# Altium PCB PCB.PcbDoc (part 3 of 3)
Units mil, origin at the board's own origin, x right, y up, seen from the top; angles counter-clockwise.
Board outline 3613 x 4415 mil, 2 copper layers (Top Layer, Bottom Layer), stack 62 mil thick; 332 components, 200 nets, 890 pads, 1069 vias.
Unrouted connection lines stored in the file: 1.
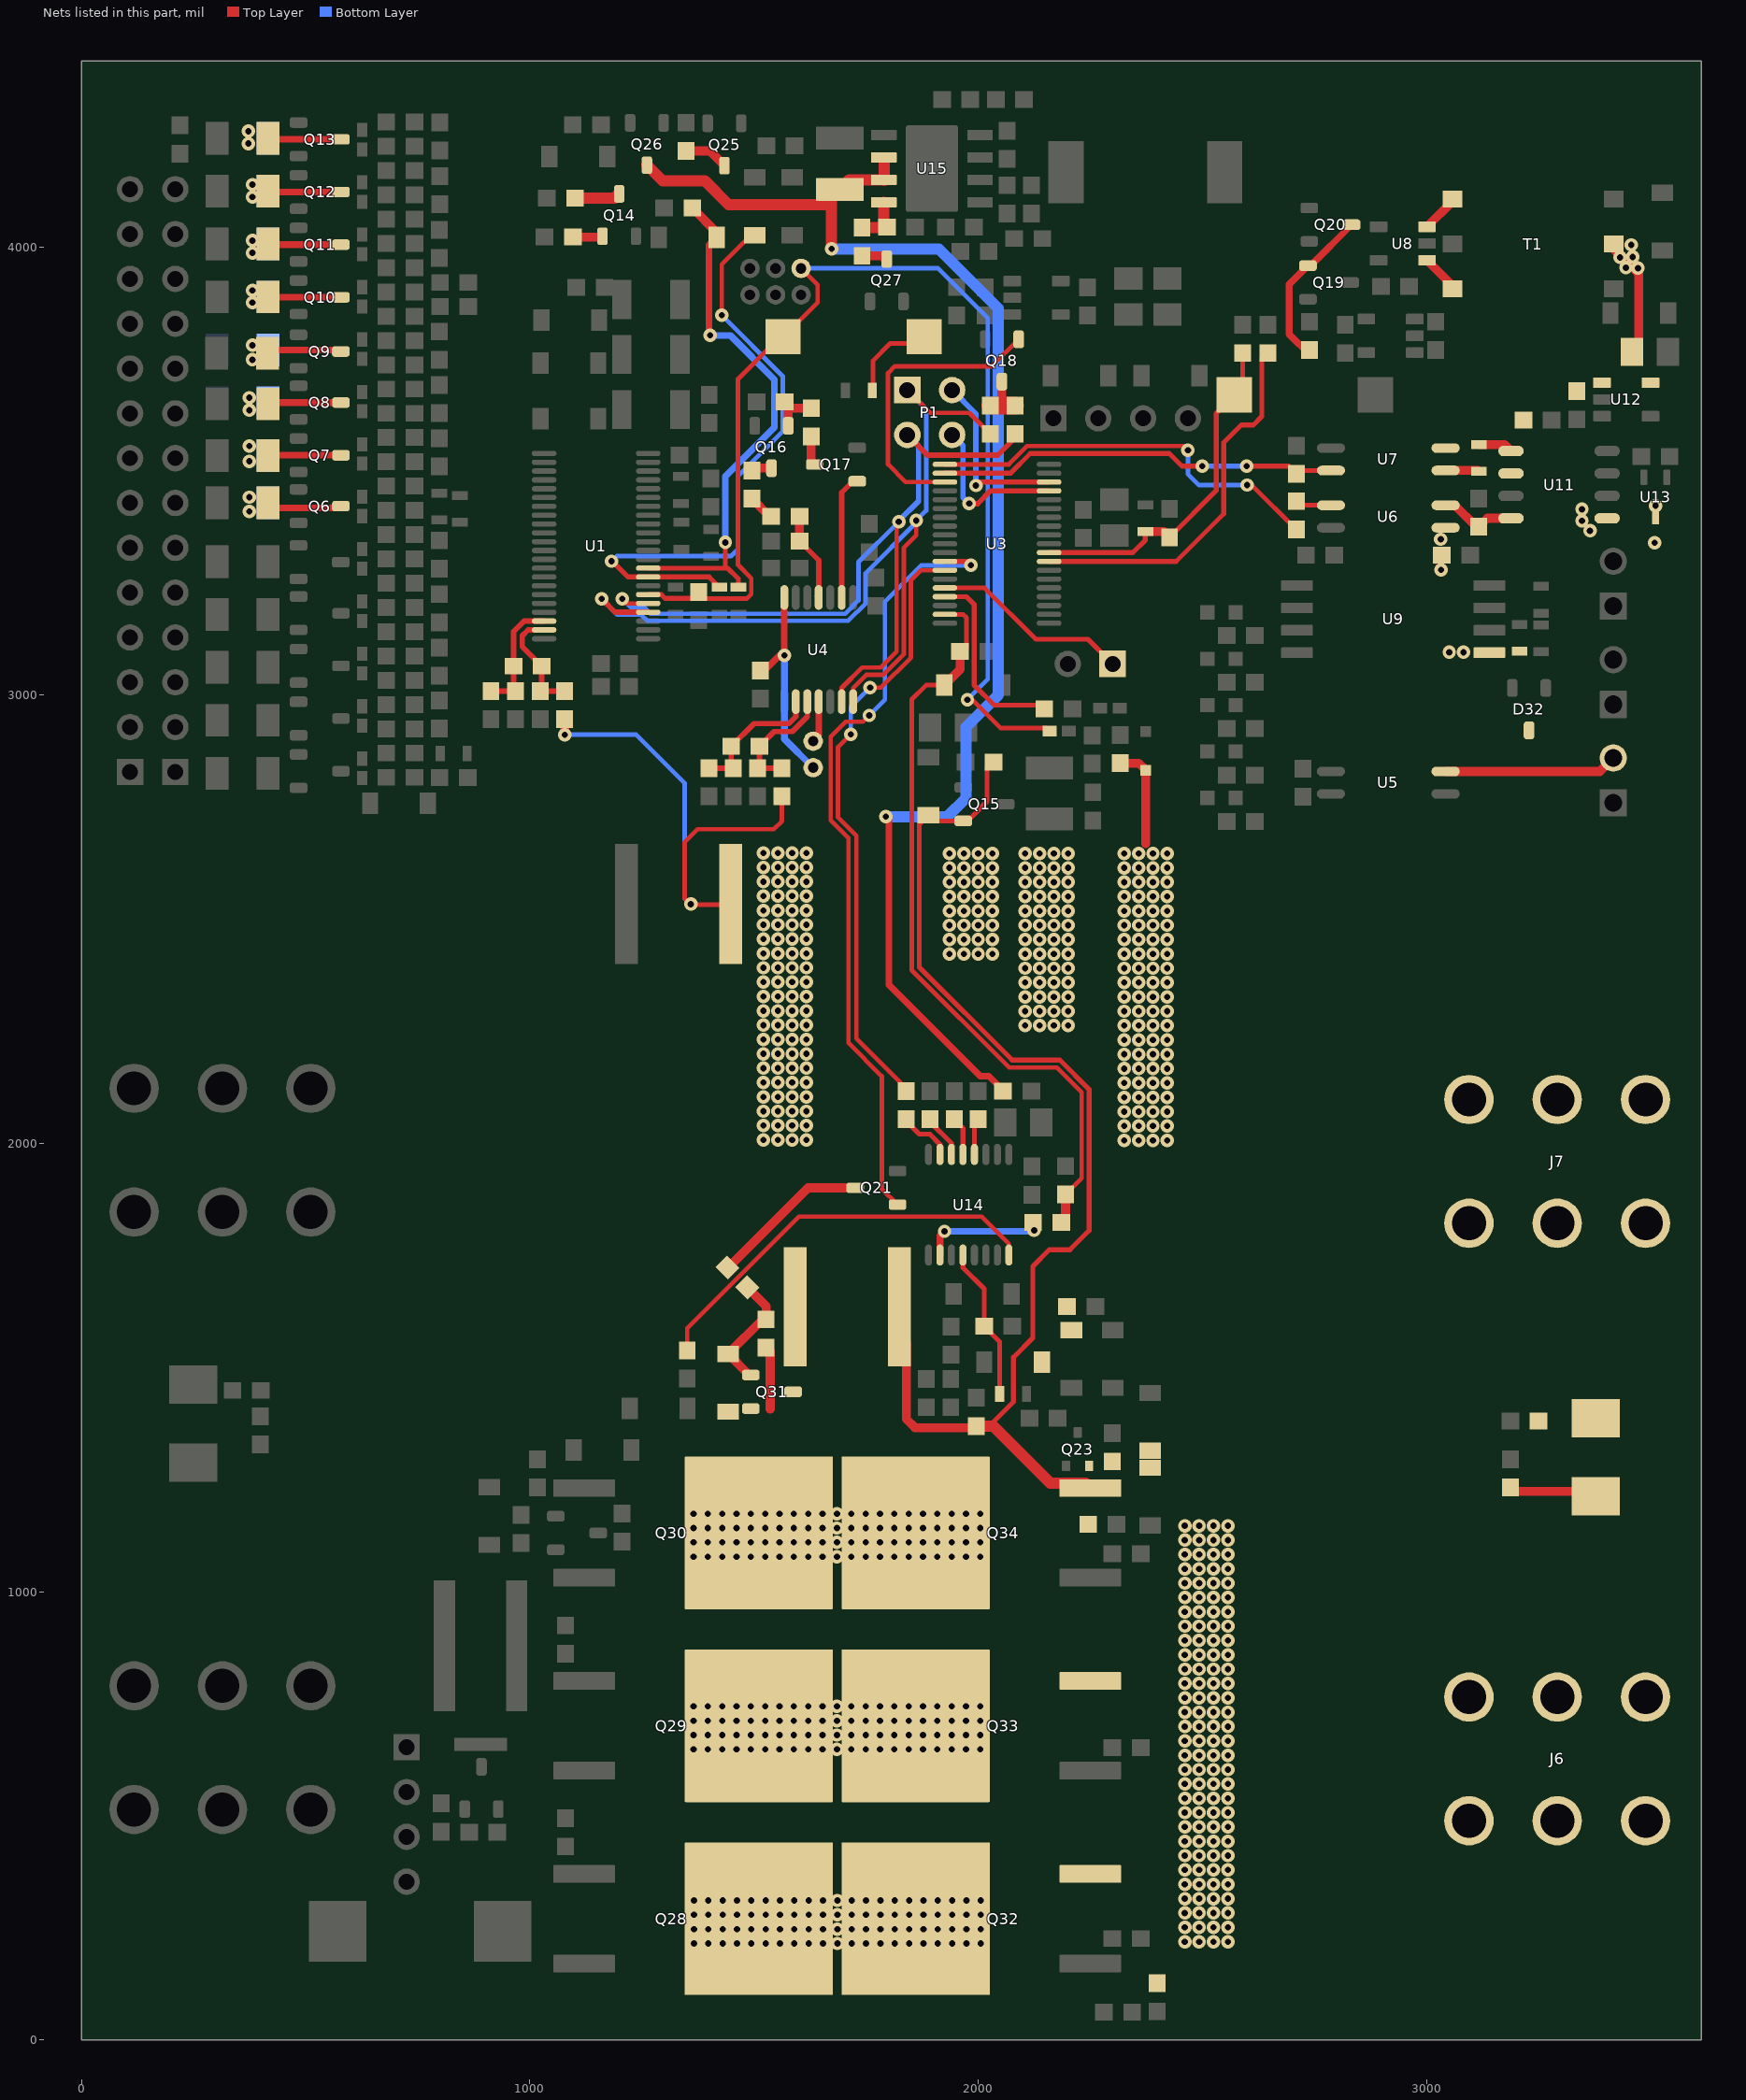
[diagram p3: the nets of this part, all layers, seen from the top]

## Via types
v1: diameter 30, hole 14, Top Layer to Bottom Layer, 1060 vias
v2: diameter 19.68, hole 7.87, Top Layer to Bottom Layer, tented both sides, 4 vias
v3: diameter 19.68, hole 7.87, Top Layer to Bottom Layer, 4 vias
v4: diameter 30, hole 14, Top Layer to Bottom Layer, tented bottom, 1 vias

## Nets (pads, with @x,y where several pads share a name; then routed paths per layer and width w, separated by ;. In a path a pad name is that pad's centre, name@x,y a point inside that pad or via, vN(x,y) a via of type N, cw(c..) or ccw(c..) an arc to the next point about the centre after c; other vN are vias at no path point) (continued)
NetQ6_3: Q6.3 R22.1 R23.1 | length 160.9
  Top Layer w15: R22.1@417.64,3418.06 Q6.3@578.49,3418.06
  other v1: 374,3410 374,3442
NetQ7_3: Q7.3 R24.1 R25.1 | length 161.5
  Top Layer w15: R24.1@417.03,3535.54 Q7.3@578.49,3535.54
  other v1: 374,3522 374,3556
NetQ8_3: Q8.3 R26.1 R27.1 | length 162.1
  Top Layer w15: R26.1@416.43,3653.01 Q8.3@578.49,3653.01
  other v1: 374,3636 374,3664
NetQ9_3: Q9.3 R28.1 R29.1 | length 162.3
  Top Layer w15: R28.1@416.17,3770.49 Q9.3@578.49,3770.49
  other v1: 380.76,3748.6 381,3781
NetQ10_3: Q10.3 R39.1 R40.1 | length 161.7
  Top Layer w15: R39.1@416.78,3887.97 Q10.3@578.49,3887.97
  other v1: 381,3876 381,3903.5
NetQ11_3: Q11.3 R41.1 R42.1 | length 161.1
  Top Layer w15: R41.1@417.38,4005.45 Q11.3@578.49,4005.45
  other v1: 381,3987.04 381,4014.54
NetQ12_3: Q12.3 R43.1 R44.1 | length 160.5
  Top Layer w15: R43.1@417.99,4122.92 Q12.3@578.49,4122.92
  other v1: 381,4112 381,4139.5
NetQ13_3: Q13.3 R45.1 R46.1 | length 159.9
  Top Layer w15: R45.1@418.59,4240.4 Q13.3@578.49,4240.4
  other v1: 372,4231 372,4258.5
NetQ14_1: Q14.1 R47.2 | length 64.3
  Top Layer w20: R47.2@1095.8,4022.42 Q14.1@1160.15,4022.42
NetQ14_3: Q14.3 R48.2 | length 101.2
  Top Layer w25: R48.2@1100.8,4109.42 1188.42,4109.42 Q14.3@1198,4119
NetQ16_1: Q16.1 R69.2 R70.1 | length 110.8
  Top Layer w20: R69.2@1568.5,3655 R69.2@1576.4,3647.09 ; Q16.1@1576.4,3601.24 R69.2@1576.4,3647.09 ; R70.1@1627.4,3640.53 1582.97,3640.53 R69.2@1576.4,3647.09
NetQ16_3: Q16.3 R71.1 | length 46.2
  Top Layer w20: R71.1@1495,3501.5 1500.26,3506.76 Q16.3@1539,3506.76
NetQ17_1: Q17.1 U4.2 | length 269.8
  Top Layer w12: U4.2@1695.58,3218.17 1695.58,3452.58 Q17.1@1720.6,3477.6
NetQ17_3: Q17.3 R70.2 | length 66
  Top Layer w20: R70.2@1627.4,3577.54 1627.4,3523.35 Q17.3@1635.76,3515
NetQ18_1: Q18.1 U3.22 | length 679.5
  Top Layer w10: U3.22@1925.86,3475.8 1838.2,3475.8 1799,3515 1799,3719 1814,3734 2030.16,3734 Q18.1@2090.4,3794.24
  Top Layer w12: Q18.1@2090.4,3784.4 Q18.1@2090.4,3794.24
NetQ18_3: Q18.3 R81.1 R83.1 | length 107.2
  Top Layer w20: 2053,3647.51 Q18.3@2053,3699.76
  Top Layer w40: R81.1@2027.16,3646.08 R83.1@2082.16,3646.08
NetQ19_1: Q19.1 Q20.3 R87.2 | length 369.3
  Top Layer w15: R87.2@2739,3760.5 2694,3805.5 2694,3916.65 Q19.1@2735.76,3958.4 2741.65,3958.4 Q20.3@2833.24,4050
NetQ21_3: Q21.3 R104.1 | length 358
  Top Layer w20: R104.1@1441.79,1722.28 1620.5,1901 Q21.3@1725.76,1901
NetQ25_3: Q25.3 R122.1 | length 99.6
  Top Layer w20: R122.1@1348,4214.5 1401.25,4214.5 Q25.3@1434,4181.76
NetQ27_3: Q27.3 R126.2 | length 59.7
  Top Layer w20: R126.2@1741,3980.5 1784.74,3980.5 Q27.3@1796,3969.24
NetQ31_3: Q31.3 R132.2 R133.2
NetR68_1: R68.1 S1.2 | length 196.4
  Top Layer w10: R68.1@1765.5,3680 1765.5,3746.5 1804,3785 S1.2@1879.48,3785
NetR71_2: R71.2 R72.1 | length 59.9
  Top Layer w20: R71.2@1495,3438.5 1534.5,3399 R72.1@1538.5,3399
NetR72_2: R72.2 R73.2 U4.4 | length 203.5
  Top Layer w12: R73.2@1601.5,3344 1644.4,3301.09 U4.4@1644.4,3218.17 U4.4@1640.91,3221.66
  Top Layer w20: R73.2@1601.5,3344 R72.2@1601.5,3399
NetR86_1: R86.1 U6.1 | length 80.8
  Top Layer w10: R86.1@2709.93,3433 2718.93,3424 U6.1@2787.05,3424
NetR90_1: R90.1 U6.4 U11.4 | length 167.5
  Top Layer w20: U6.4@3042.95,3424 3063,3424 R90.1@3111,3376 ; R90.1@3117,3376 3136,3395 U11.4@3188.72,3395
NetR91_1: R91.1 U7.1 | length 74.9
  Top Layer w20: U7.1@3042.95,3501.5 3115,3501.5 R91.1@3117,3499.5
NetR91_2: R91.2 U11.1 | length 77.7
  Top Layer w20: R91.2@3117,3559.5 3174.22,3559.5 U11.1@3188.72,3545
NetR95_2: R95.2 U14.7 | length 123.6
  Top Layer w11: R95.2@1839.4,2053.95 1839.4,2050.15 1868.66,2020.89 1892.11,2020.89 1914.92,1998.08 U14.7@1914.92,1975.41
NetR96_2: R96.2 U14.6 | length 92.4
  Top Layer w11: R96.2@1892.9,2048.1 1940.51,2000.49 U14.6@1940.51,1975.41
NetR97_2: R97.2 U14.5 | length 86.7
  Top Layer w11: R97.2@1946.4,2053.95 1966.1,2034.25 U14.5@1966.1,1975.41
NetR99_2: R99.2 U14.4 | length 70.3
  Top Layer w11: U14.4@1991.69,1975.41 R99.2@1991.69,2045.75
NetR100_1: R100.1 U14.16 | length 920.7
  Top Layer w10: R100.1@1351,1538.5 1351,1588 1600,1837 2008,1837 2068.46,1776.54 U14.16@2068.46,1751
NetR101_1: R101.1 U14.10 | length 258
  Top Layer w15: U14.10@1914.92,1751 1914.92,1793.92 v1(1925,1804)
  Bottom Layer w15: v1(1925,1804) 2123,1804 v1(2125,1806)
NetR107_2: R107.2 R108.1 U14.12 | length 343.9
  Top Layer w11: U14.12@1966.1,1751 1966.1,1722.9 2013.5,1675.5 R107.2@2013.5,1592 2048,1557.5 R108.1@2048,1441
NetR125_1: R125.1 R126.1 U15.4 | length 100.4
  Top Layer w25: R126.1@1741,4043.5 1781.43,4043.5 1789.72,4051.79 U15.4@1789.72,4100
NetRT4_1: RT4.1 U4.11 | length 93.5
  Top Layer w15: RT4.1@1632,2897.53 1644.4,2909.93 U4.11@1644.4,2985.89
NetT1_1: T1.1 U8.3 | length 85.2
  Top Layer w20: U8.3@3001.45,4045.4 3058.39,4102.35 T1.1@3058.39,4107
NetT1_3: T1.3 U8.1 | length 87.2
  Top Layer w20: U8.1@3001.45,3970.6 3058.39,3913.65 T1.3@3058.39,3907
Pack+: C69.1 C71.1 D16.1 D40.2 D43.2 D48.1 J6.1 J6.2 J6.3 J6.4 J6.5 J6.6 Q15.2 Q23.2 Q32.3 Q33.3 Q34.3 R59.2 R110.2 R114.1 R115.2 R132.1 R133.1 | length 2751.4
  Top Layer w11: Q15.2@1966.77,2719.6 1901.95,2719.6 D16.1@1889.02,2732.53 1868.5,2712.02 1868.5,2393.33 2075.83,2186 2182.33,2186 2247.5,2120.83 2247.5,1805.5 2205,1763 2159,1763 2122,1726 2122,1566 2079,1523 2079,1424.01 2024.5,1369.5 ; Q15.2@1976.6,2719.6 2020,2763 2020,2836.49 R59.2@2034.51,2851 ; Q34.3@2239.55,1231.21 Q34.3@2250.34,1231.21
  Top Layer w20: R132.1@1840,1554.14 1840,1385 1859,1366 R115.2@1980.5,1366 ; C71.1@3182,1224 D48.1@3359.99,1224
  Top Layer w25: R115.2@1996,1369.5 2024.5,1369.5 2033.5,1369.5 2161,1242 Q34.3@2239.55,1242
  other v1: 2461,219 2493,219 2525,219 2557,219 2461,251 2493,251 2525,251 2557,251 2461,283 2493,283 2525,283 2557,283 2461,315 2493,315 2525,315 2557,315 2461,347 2493,347 2525,347 2557,347 2461,379 2493,379 2525,379 2557,379 2461,411 2493,411 2525,411 2557,411 2461,443 2493,443 2525,443 2557,443 2461,475 2493,475 2525,475 2557,475 2461,507 2493,507 2525,507 2557,507 2461,539 2493,539 2525,539 2557,539 2461,571 2493,571 2525,571 2557,571 2461,603 2493,603 2525,603 2557,603 2461,635 2493,635 2525,635 2557,635 2461,667 2493,667 2525,667 2557,667 2461,699 2493,699 2525,699 2557,699 2461,731 2493,731 2525,731 2557,731 2461,763 2493,763 2525,763 2557,763 2461,795 2493,795 2525,795 2557,795 2461,827 2493,827 2525,827 2557,827 2461,859 2493,859 2525,859 2557,859 2461,891 2493,891 2525,891 2557,891 2461,923 2493,923 2525,923 2557,923 2461,955 2493,955 2525,955 2557,955 2461,987 2493,987 2525,987 2557,987 2461,1019 2493,1019 2525,1019 2557,1019 2461,1051 2493,1051 2525,1051 2557,1051 2461,1083 2493,1083 2525,1083 2557,1083 2461,1115 2493,1115 2525,1115 2557,1115 2461,1147 2493,1147 2525,1147 2557,1147
Pack-: C70.2 D21.2 D39.2 D41.2 D48.2 J7.1 J7.2 J7.3 J7.4 J7.5 J7.6 R66.1 R112.1 R118.2 R119.2 R120.1 R127.1 | length 1356.2
  Top Layer w10: R118.2@1429,2533 1359,2533 1345,2547 1345,2672 1374,2701 1544,2701 1562.33,2719.33 R127.1@1562.33,2774.5
  Top Layer w20: v1(1078,2912) R120.1@1078,2945.5 ; R66.1@2317,2848.5 2358.19,2848.5 D21.2@2374,2832.69 2374,2669
  Bottom Layer w10: v1(1078,2912) 1237,2912 1345,2804 1345,2547 v1@1359,2533
  other v1: 2326,2007 2358,2007 2390,2007 2422,2007 1521,2008 1553,2008 1585,2008 1617,2008 2326,2039 2358,2039 2390,2039 2422,2039 1521,2040 1553,2040 1585,2040 1617,2040 2326,2071 2358,2071 2390,2071 2422,2071 1521,2072 1553,2072 1585,2072 1617,2072 2326,2103 2358,2103 2390,2103 2422,2103 1521,2104 1553,2104 1585,2104 1617,2104 2326,2135 2358,2135 2390,2135 2422,2135 1521,2136 1553,2136 1585,2136 1617,2136 2326,2167 2358,2167 2390,2167 2422,2167 1521,2168 1553,2168 1585,2168 1617,2168 2326,2199 2358,2199 2390,2199 2422,2199 1521,2200 1553,2200 1585,2200 1617,2200 2326,2231 2358,2231 2390,2231 2422,2231 1521,2232 1553,2232 1585,2232 1617,2232 2105,2263 2137,2263 2169,2263 2201,2263 2326,2263 2358,2263 2390,2263 2422,2263 1521,2264 1553,2264 1585,2264 1617,2264 2105,2295 2137,2295 2169,2295 2201,2295 2326,2295 2358,2295 2390,2295 2422,2295 1521,2296 1553,2296 1585,2296 1617,2296 2105,2327 2137,2327 2169,2327 2201,2327 2326,2327 2358,2327 2390,2327 2422,2327 1521,2328 1553,2328 1585,2328 1617,2328 2105,2359 2137,2359 2169,2359 2201,2359 2326,2359 2358,2359 2390,2359 2422,2359 1521,2360 1553,2360 1585,2360 1617,2360 2105,2391 2137,2391 2169,2391 2201,2391 2326,2391 2358,2391 2390,2391 2422,2391 1521,2392 1553,2392 1585,2392 1617,2392 1936,2423 1968,2423 2000,2423 2032,2423 2105,2423 2137,2423 2169,2423 2201,2423 2326,2423 2358,2423 2390,2423 2422,2423 1521,2424 1553,2424 1585,2424 1617,2424 1936,2455 1968,2455 2000,2455 2032,2455 2105,2455 2137,2455 2169,2455 2201,2455 2326,2455 2358,2455 2390,2455 2422,2455 1521,2456 1553,2456 1585,2456 1617,2456 1936,2487 1968,2487 2000,2487 2032,2487 2105,2487 2137,2487 2169,2487 2201,2487 2326,2487 2358,2487 2390,2487 2422,2487 1521,2488 1553,2488 1585,2488 1617,2488 1936,2519 1968,2519 2000,2519 2032,2519 2105,2519 2137,2519 2169,2519 2201,2519 2326,2519 2358,2519 2390,2519 2422,2519 1521,2520 1553,2520 1585,2520 1617,2520 1359,2534 1936,2551 1968,2551 2000,2551 2032,2551 2105,2551 2137,2551 2169,2551 2201,2551 2326,2551 2358,2551 2390,2551 2422,2551 1521,2552 1553,2552 1585,2552 1617,2552 1936,2583 1968,2583 2000,2583 2032,2583 2105,2583 2137,2583 2169,2583 2201,2583 2326,2583 2358,2583 2390,2583 2422,2583 1521,2584 1553,2584 1585,2584 1617,2584 1936,2615 1968,2615 2000,2615 2032,2615 2105,2615 2137,2615 2169,2615 2201,2615 2326,2615 2358,2615 2390,2615 2422,2615 1521,2616 1553,2616 1585,2616 1617,2616 1936,2647 1968,2647 2000,2647 2032,2647 2105,2647 2137,2647 2169,2647 2201,2647 2326,2647 2358,2647 2390,2647 2422,2647 1521,2648 1553,2648 1585,2648 1617,2648
Pack_ADC: C50.1 D35.1 R101.2 R102.2 U3.37 | length 1687.5
  Top Layer w10: D35.1@1924.53,3022.59 1883.59,3022.59 1852,2991 1852,2386.5 2069,2169.5 2175.5,2169.5 2231,2114 2231,1922.5 R102.2@2195,1886.5 ; U3.37@1925.86,3180.52 1966.42,3180.52 1974,3172.94 C50.1@1974,3104
  Top Layer w20: D35.1@1924.53,3022.59 1959.5,3057.56 C50.1@1959.5,3098 ; R101.2@2195,1833.5 R102.2@2195,1886.5
PDCHG: Q21.1 U3.31 | length 1755.5
  Top Layer w10: v1(1757,2955) 1743,2941 1704,2941 1671,2908 1671,2721.37 1710.63,2681.74 1710.63,2224.37 1785,2150 1785,1898.84 Q21.1@1820.24,1863.6
  Top Layer w12: U3.31@1925.86,3298.63 v1@1975.63,3298.63
  Bottom Layer w10: v1(1757,2955) 1792,2990 1792,3209 1873,3290 v1(1984,3290)
PDCHG_G: D37.2 Q31.1 R104.2 R106.1 | length 272
  Top Layer w20: R104.2@1485.27,1678.73 1527,1637 R106.1@1527,1607.5 1519.03,1607.5 D37.2@1442,1530.47 Q31.1@1489.07,1483.4
PDCHG_S: D37.1 Q28.2 Q29.2 Q30.2 Q31.2 Q32.2 Q33.2 Q34.2 R106.2 | length 141.2
  Top Layer w20: R106.2@1527,1544.5 1536,1535.5 1536,1407
  other v1: 1366,215 1398,215 1430,215 1462,215 1494,215 1526,215 1558,215 1590,215 1622,215 1654,215 1686,215 1718,215 1750,215 1782,215 1814,215 1846,215 1878,215 1910,215 1942,215 1974,215 2006,215 1366,247 1398,247 1430,247 1462,247 1494,247 1526,247 1558,247 1590,247 1622,247 1654,247 1686,247 1718,247 1750,247 1782,247 1814,247 1846,247 1878,247 1910,247 1942,247 1974,247 2006,247 1366,279 1398,279 1430,279 1462,279 1494,279 1526,279 1558,279 1590,279 1622,279 1654,279 1686,279 1718,279 1750,279 1782,279 1814,279 1846,279 1878,279 1910,279 1942,279 1974,279 2006,279 1366,311 1398,311 1430,311 1462,311 1494,311 1526,311 1558,311 1590,311 1622,311 1654,311 1686,311 1718,311 1750,311 1782,311 1814,311 1846,311 1878,311 1910,311 1942,311 1974,311 2006,311 1365,648 1397,648 1429,648 1461,648 1493,648 1525,648 1557,648 1589,648 1621,648 1653,648 1685,648 1717,648 1749,648 1781,648 1813,648 1845,648 1877,648 1909,648 1941,648 1973,648 2005,648 1365,680 1397,680 1429,680 1461,680 1493,680 1525,680 1557,680 1589,680 1621,680 1653,680 1685,680 1717,680 1749,680 1781,680 1813,680 1845,680 1877,680 1909,680 1941,680 1973,680 2005,680 1365,712 1397,712 1429,712 1461,712 1493,712 1525,712 1557,712 1589,712 1621,712 1653,712 1685,712 1717,712 1749,712 1781,712 1813,712 1845,712 1877,712 1909,712 1941,712 1973,712 2005,712 1365,744 1397,744 1429,744 1461,744 1493,744 1525,744 1557,744 1589,744 1621,744 1653,744 1685,744 1717,744 1749,744 1781,744 1813,744 1845,744 1877,744 1909,744 1941,744 1973,744 2005,744 1365,1078 1397,1078 1429,1078 1461,1078 1493,1078 1525,1078 1557,1078 1589,1078 1621,1078 1653,1078 1685,1078 1717,1078 1749,1078 1781,1078 1813,1078 1845,1078 1877,1078 1909,1078 1941,1078 1973,1078 2005,1078 1365,1110 1397,1110 1429,1110 1461,1110 1493,1110 1525,1110 1557,1110 1589,1110 1621,1110 1653,1110 1685,1110 1717,1110 1749,1110 1781,1110 1813,1110 1845,1110 1877,1110 1909,1110 1941,1110 1973,1110 2005,1110 1365,1142 1397,1142 1429,1142 1461,1142 1493,1142 1525,1142 1557,1142 1589,1142 1621,1142 1653,1142 1685,1142 1717,1142 1749,1142 1781,1142 1813,1142 1845,1142 1877,1142 1909,1142 1941,1142 1973,1142 2005,1142 1365,1174 1397,1174 1429,1174 1461,1174 1493,1174 1525,1174 1557,1174 1589,1174 1621,1174 1653,1174 1685,1174 1717,1174 1749,1174 1781,1174 1813,1174 1845,1174 1877,1174 1909,1174 1941,1174 1973,1174 2005,1174
PMON: R95.1 U3.32 | length 1377.4
  Top Layer w10: v1(1716,2913) 1687,2884 1687,2728 1728.5,2686.5 1728.5,2234.5 1835.97,2127.03 R95.1@1839.4,2127.03 ; v1(1759,3017) 1783,3017 1850,3084 1850,3257 1871.94,3278.94 U3.32@1925.86,3278.94 ; R95.1@1834.57,2122.21 R95.1@1839.4,2117.39
  Bottom Layer w10: v1@1716,2904 v1(1716,2913) 1716,2974 v1(1759,3017)
PRES: P6.1 U3.34 | length 444.4
  Top Layer w10: U3.34@1925.86,3239.57 2014.43,3239.57 2129,3125 2245,3125 P6.1@2300,3070
REG25: C37.1 RT4.2 U4.7 | length 464.7
  Top Layer w15: C37.1@1523.5,3055.5 1557,3089 v1(1568,3089) 1567.63,3089.37 U4.7@1567.63,3218.17
  Bottom Layer w15: v1(1568,3089) 1568,2902.47 RT4.2@1632,2838.47
REGOUT: C30.1 D46.2 U1.8 | length 1396.5
  Top Layer w10: v1(1428,3848) 1428,3961.88 D46.2@1502,4035.88
  Top Layer w11: v1(1182,3299) 1184,3299 1219.03,3263.97 U1.8@1263.98,3263.97 1400.03,3263.97 C30.1@1423,3241
  Bottom Layer w10: v1(1182,3299) 1193.5,3310.5 1448.5,3310.5 1464,3326 1464,3488.33 1564,3588.33 1564,3712 v1(1428,3848)
REGSRC: C13.1 D11.1 R49.2 U1.9 | length 1193.6
  Top Layer w11: U1.9@1263.98,3283.66 1441.34,3283.66 1465,3260 C13.1@1465,3241 ; 1436,3284.66 v1(1436,3341)
  Top Layer w15: v1(1402,3803) 1399.5,3805.5 1399.5,4005.03 D11.1@1416.47,4022
  Top Layer w20: R49.2@1362.5,4087 1416.47,4033.03 D11.1@1416.47,4022
  Bottom Layer w15: v1(1402,3803) 1446.84,3803 1545.5,3704.34 1545.5,3598 1436,3488.5 v1(1436,3341)
RXD: R88.1 U3.21 U7.4 | length 890.8
  Top Layer w11: U3.21@1925.86,3495.48 2072.25,3495.48 2116.27,3539.5 2426.5,3539.5 2455,3511 v1(2500,3511) ; v1(2599,3511) 2693,3511 R88.1@2710,3494 ; R88.1@2717.5,3501.5 U7.4@2787.05,3501.5
  Bottom Layer w11: v1(2500,3511) v1(2599,3511)
SBCLK: R85.1 U3.8 | length 848.8
  Top Layer w11: U3.8@2158.14,3298.63 2441.63,3298.63 2548,3405 2548,3564 2587,3603 2614,3603 2633,3622 2633,3750.5 R85.1@2646,3763.5
SBIO: C38.1 R82.1 R84.1 S2.1 U3.9 | length 795.7
  Top Layer w11: U3.9@2158.14,3318.31 2345.31,3318.31 2373,3346 C38.1@2373,3365 ; R82.1@2427,3352.5 2531,3456.5 2531,3628.48 2571.52,3669 2590,3687.48 R84.1@2590,3763.5 ; S2.1@2569,3656 S2.1@2581.7,3656
  Top Layer w20: C38.1@2373,3365 2414.5,3365 R82.1@2427,3352.5
SCL: P1.3 R83.2 U1.5 U4.13 | length 1812
  Top Layer w10: v1(1206,3215) 1216.08,3204.92 U1.5@1263.98,3204.92 ; U4.13@1695.58,2985.89 1695.58,3016.58 1741,3062 1782.37,3062 1818,3097.63 1818,3382 v1(1823,3387)
  Top Layer w12: P1.3@1842,3581 1887,3536 2044,3536 2082.16,3574.16 R83.2@2082.16,3583.09
  Bottom Layer w10: v1(1206,3215) 1225,3196 1254.63,3196 1268.63,3182 1703.37,3182 1733,3211.63 1733,3297 v1(1823,3387)
  Bottom Layer w12: v1(1823,3387) 1823,3389.18 1867,3433.18 1867,3556 P1.3@1842,3581
SCL-Gauge: P1.4 U3.16 | length 385.8
  Top Layer w12: P1.4@1940,3602 P1.4@1958.91,3583.09 ; v1(1980,3427.59) 1998.79,3427.59 2027.32,3456.11 U3.16@2158.14,3456.11
  Bottom Layer w12: P1.4@1942,3581 1966,3557 1966,3441.59 v1(1980,3427.59)
SDA: P1.1 R81.2 U1.4 U4.14 | length 2001.5
  Top Layer w10: U4.14@1721.17,2985.89 1721.17,3016.17 1751,3046 1789,3046 1834,3091 1834,3329 1862,3357 v1(1862,3390) ; P1.1@1842,3681 1893,3630 1980.25,3630 R81.2@2027.16,3583.09
  Top Layer w12: v1(1160,3215) 1189.77,3185.23 U1.4@1263.98,3185.23
  Bottom Layer w10: v1(1160,3215) 1195,3180 1248,3180 1262,3166 1710,3166 1749,3205 1749,3272.63 1862,3385.63 v1(1862,3390) 1884,3412 1884,3639 P1.1@1842,3681
SDA-Gauge: P1.2 U3.17 | length 442.6
  Top Layer w10: P1.2@1940,3677 P1.2@1940,3702
  Top Layer w12: v1(1995,3468) 2002.8,3475.8 U3.17@2158.14,3475.8
  Bottom Layer w12: P1.2@1940,3702 P1.2@1951.5,3690.5 ; P1.2@1942,3681 1995,3628 v1(1995,3468)
SGND: C41.2 C43.2 C45.1 C46.2 C47.2 D32.3 J5.2 T1.5 U5.2 U6.3 U7.2 U9.5 U11.2 U11.5 U12.1 U12.5 U13.3 | length 653.3
  Top Layer w15: C43.2@3022,3300.5 C43.2@3034.5,3313
  Top Layer w20: U5.2@3042.95,2830 3387,2830 J5.2@3417,2860 ; T1.5@3418.24,4007 3418.24,3995.76 3474,3940 C46.2@3474,3781
  other v1: 3051,3096 3083,3096 3033,3280 3509,3340 3032,3348 3365,3367 3347,3389 3347,3415 3511,3423 3472,3953 3445,3954 3432,3977 3460,3978 3457,4005
SRN: C60.1 C61.2 R127.2 U4.10 | length 272.3
  Top Layer w12: R127.2@1562.33,2837.5 C61.2@1508,2837.5 1511.99,2841.49 C60.1@1511.99,2886 1544.99,2919 1585.46,2919 1618.81,2952.36 U4.10@1618.81,2985.89
SRN_M: C56.1 C57.2 R120.2 U1.43 | length 251.9
  Top Layer w12: U1.43@1031.69,3145.86 995.86,3145.86 983,3133 983,3108.5 C56.1@1026.5,3065 1026.5,3013.64 1022.36,3009.5 C57.2@1023,3009.5 R120.2@1077,3009.5
SRP: C58.1 C60.2 R124.2 U4.9 | length 310
  Top Layer w12: R124.2@1399.33,2837.5 C58.1@1453.6,2837.5 1449,2842.1 C60.2@1449,2886 1500,2937 1578,2937 1593.22,2952.22 U4.9@1593.22,2985.89
SRP_M: C55.1 C56.2 R117.2 U1.42 | length 267.3
  Top Layer w12: R117.2@913.07,3009.5 C55.1@968,3009.5 963.5,3013.99 C56.2@963.5,3065 963.5,3142.05 987,3165.55 U1.42@1031.69,3165.55
TS1: C29.1 D22.1 RT1.2 S1.1 U1.6 | length 2633.3
  Top Layer w10: C29.1@1377,3230.5 1391.5,3216 1484,3216 1494,3226 1494,3261 1464.14,3290.86 1464.14,3705.44 S1.1@1543.7,3785 ; S1.1@1564.52,3785 1551,3785 1642,3876 1642,3915.53 RT1.2@1605,3952.53 ; v1(1976,2990) 1987,2990 2050,2927 2152.35,2927 D22.1@2159.35,2920
  Top Layer w11: U1.6@1263.98,3224.6 1293.4,3224.6 1302,3216 1362.5,3216 C29.1@1377,3230.5
  Bottom Layer w10: RT1.2@1605,3952.53 1910.47,3952.53 2021.5,3841.5 2021.5,3035.5 v1(1976,2990)
TXD: R86.2 U3.20 | length 909.1
  Top Layer w10: U3.20@1925.86,3515.17 2068.6,3515.17 2109.43,3556 2459,3556 v1(2468,3547) ; v1(2600,3469) 2610.94,3469 R86.2@2709.93,3370
  Bottom Layer w10: v1(2468,3547) 2468,3494 2493,3469 v1(2600,3469)
VDD: C59.1 Q26.3 R98.2 U15.2 U15.3 | length 3173.7
  Top Layer w15: v1@1800.63,2722.87 1800.63,2354 2004.5,2150.13 2024.19,2150.13 2055.5,2118.82 R98.2@2055.5,2117
  Top Layer w25: Q26.3@1261,4182.76 1295.76,4148 1390,4148 1443.09,4094.91 1657,4094.91 ; v1(1673,3996) C59.1@1673,4110.91 ; C59.1@1691,4128.91 1712.09,4150 U15.3@1789.72,4150 ; U15.3@1790,4149 U15.2@1790,4199
  Bottom Layer w25: v1(1673,3996) 1912,3996 2045,3863 2045,3000.94 1972.53,2928.47 1972.53,2770.2 1931.32,2729 1794,2729 v1(1794,2729.5)
Wake: R61.2 U3.35 | length 427.3
  Top Layer w11: U3.35@1925.86,3219.89 1974.11,3219.89 1991,3203 1991,3023 2036,2978 R61.2@2147.5,2978
pads on no net: U1.21 U1.22 U1.23 U3.13 U3.14 U3.15 U3.19 U3.26 U3.28 U3.29 U3.30 U3.36 U3.38 U14.3 U14.13 U14.14 U14.15 U15.6 U15.9@1897,4175

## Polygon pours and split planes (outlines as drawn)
3V3 on Top Layer "TOP_LAYER_3V3_P184" (solid, remove dead copper, pour order 184): 2034.47,3869 2034.47,3771 1933.3,3771 1933.3,3869
CHG_S on Top Layer "TOP_LAYER_CHG_S_P078" (solid, remove dead copper, pour order 78): 949,1143 873,1143 873,1099 928,1041 1277,1041 1277,1143
GND on Top Layer "TOP_LAYER_GND_P194" (solid, remove dead copper, pour order 194): 1801,1999 1801,1854 2139,1854 2139,1999
Pack- on Top Layer "TOP_LAYER_PACK-_P192" (solid, remove dead copper, pour order 192): 1420,2675 1800,2675 1800,1875 1574,1875 1544,1845 1544,1511 1420,1511
NetC20_1 on Top Layer "TOP_LAYER_NETC20_1_P188" (solid, remove dead copper, pour order 188): 2105.87,2868 2105.87,2814 2187.3,2814 2237.3,2764 2275,2764 2275,2868
CHG_S on Top Layer "TOP_LAYER_CHG_S_P174" (solid, pour order 174): 991,611 938,558 938,424 982,424 1015,457 1015,587
NetC54_1 on Top Layer "TOP_LAYER_NETC54_1_P172" (solid, remove dead copper, pour order 172): 825,508 825,611 754,682 695,682 695,508
GND on Top Layer "TOP_LAYER_GND_P170" (solid, remove dead copper, pour order 170): 825,485 825,414 771,360 771,318 678,318 678,485
Pack+ on Top Layer "TOP_LAYER_PACK+_P080" (solid, remove dead copper, pour order 80): 2408,1311 2258,1311 2216,1269 2216,1249 2408,1249
Pack+ on Top Layer "TOP_LAYER_PACK+_P064" (solid, remove dead copper, pour order 64): 3561,1255 2182,1255 2182,106 3561,106
Pack- on Top Layer "TOP_LAYER_PACK-_P062" (solid, remove dead copper, pour order 62): 3561,2673 1871,2673 1871,1345 3561,1345
GND on Top Layer "TOP_LAYER_GND_P058" (solid, remove dead copper, pour order 58): 2686,3631 2686,3748 2686,4057 3047,4057 3047,3752 2926,3631
GND on Top Layer "TOP_LAYER_GND_P054" (solid, remove dead copper, pour order 54): 2796.21,3613.21 2748,3565 2748,3535 2819,3535 2819,3590.43
GND on Top Layer "TOP_LAYER_GND_P052" (solid, remove dead copper, pour order 52): 2780,3388 2758.71,3388 2740,3369.29 2740,3338 2597,3338 2597,3316 2641,3272 2763,3272 2763,3344 2819,3344 2819,3388
GND on Top Layer "TOP_LAYER_GND_P050" (solid, remove dead copper, pour order 50): 2755,2817 2755,2833.93 2793,2871.93 2819,2871.93 2819,2817
GND on Top Layer "TOP_LAYER_GND_P048" (solid, remove dead copper, pour order 48): 2673,2887 2673,3107 2785,3107 2785,2936 2736,2887
GND on Top Layer "TOP_LAYER_GND_P046" (solid, remove dead copper, pour order 46): 2137,3911 2204,3911 2225,3890 2439,3890 2476,3927 2476,3956 2439,3993 2137,3993
BAT+ on Top Layer "TOP_LAYER_BAT+_P010" (solid, remove dead copper, pour order 10): 52,1349 52,45 634,45 634,633 cw(c734,633) 734,733 833,733 833,1349
GND on Top Layer "TOP_LAYER_GND_P008" (solid, remove dead copper, pour order 8): 1242,2673 52,2673 52,1419 1242,1419
CHG_S on Top Layer "TOP_LAYER_CHG_S_P002" (solid, remove dead copper, pour order 2): 1277,43 1277,1054 922,1054 922,752 975,699 975,476 874,375 874,43
PDCHG_S on Top Layer "TOP_LAYER_PDCHG_S_P006" (solid, remove dead copper, pour order 6): 1418,1420 1348,1350 1342,1350 1342,98 2028,98 2028,1324 1843,1324 1809,1358 1809,1420
SGND on Top Layer "TOP_LAYER_SGND_P024" (solid, remove dead copper, pour order 24): 3562,4027 3562,2694 3011,2694 3011,3571 3134,3571 3273,3710 3384,3821 3384,4027
GND on Top Layer "TOP_LAYER_GND_P040" (solid, remove dead copper, pour order 40): 2213,3521 2392,3521 2392,3411 2333,3411 2316,3394 2213,3394
GND on Top Layer "TOP_LAYER_GND_P086" (solid, remove dead copper, pour order 86): 1955,4381 1955,4275.27 1955,4020 1833,4020 1833,4180 1808,4205 1561,4205 1561,4257 1380,4257 1380,4381
GND on Top Layer "TOP_LAYER_GND_P088" (solid, remove dead copper, pour order 88): 2101,3912 2101,3959 1785,3959 1785,3855 1894,3855 1929,3890 2034.47,3890 2056.47,3912
NetQ13_3 on Top Layer "TOP_LAYER_NETQ13_3_P096" (solid, remove dead copper, pour order 96): 346,4292 599,4292 599,4206 346,4206
NetQ12_3 on Top Layer "TOP_LAYER_NETQ12_3_P100" (solid, remove dead copper, pour order 100): 346,4174.52 599,4174.52 599,4088.52 346,4088.52
NetQ11_3 on Top Layer "TOP_LAYER_NETQ11_3_P102" (solid, remove dead copper, pour order 102): 346,4057.04 599,4057.04 599,3971.04 346,3971.04
NetQ10_3 on Top Layer "TOP_LAYER_NETQ10_3_P104" (solid, remove dead copper, pour order 104): 346,3937.52 599,3937.52 599,3851.52 346,3851.52
NetQ9_3 on Top Layer "TOP_LAYER_NETQ9_3_P108" (solid, remove dead copper, pour order 108): 346,3813 599,3813 599,3727 346,3727
NetQ8_3 on Top Layer "TOP_LAYER_NETQ8_3_P110" (solid, remove dead copper, pour order 110): 346.24,3699.01 599.24,3699.01 599.24,3613.01 346.24,3613.01
NetQ7_3 on Top Layer "TOP_LAYER_NETQ7_3_P112" (solid, remove dead copper, pour order 112): 346.24,3581.54 599.24,3581.54 599.24,3495.54 346.24,3495.54
NetQ6_3 on Top Layer "TOP_LAYER_NETQ6_3_P114" (solid, remove dead copper, pour order 114): 346,3468 599,3468 599,3382 346,3382
NetQ5_3 on Top Layer "TOP_LAYER_NETQ5_3_P116" (solid, remove dead copper, pour order 116): 346,3343 599,3343 599,3257 346,3257
NetQ4_3 on Top Layer "TOP_LAYER_NETQ4_3_P118" (solid, remove dead copper, pour order 118): 346.24,3229.1 599.24,3229.1 599.24,3143.1 346.24,3143.1
NetQ3_3 on Top Layer "TOP_LAYER_NETQ3_3_P120" (solid, remove dead copper, pour order 120): 346.24,3111.63 599.24,3111.63 599.24,3025.63 346.24,3025.63
NetQ2_3 on Top Layer "TOP_LAYER_NETQ2_3_P122" (solid, remove dead copper, pour order 122): 346.24,2994.15 599.24,2994.15 599.24,2908.15 346.24,2908.15
NetQ1_3 on Top Layer "TOP_LAYER_NETQ1_3_P124" (solid, remove dead copper, pour order 124): 346,2875 599,2875 599,2789 346,2789
GND on Top Layer "TOP_LAYER_GND_P156" (solid, remove dead copper, pour order 156): 955,2888 848,2888 848,2845 830,2827 830,2796 818,2784 722,2784 722,2693 955,2693
GND on Top Layer "TOP_LAYER_GND_P158" (solid, remove dead copper, pour order 158): 1900.24,3567.7 1900.24,3154.7 2183.24,3154.7 2183.24,3567.7
NetC64_1 on Top Layer "TOP_LAYER_NETC64_1_P160" (solid, remove dead copper, pour order 160): 2100,4000 2100,4017 cw(c2138,4017) 2138,4055 2138,4095 2046,4095 2046,4055 2060,4041 2060,4000
NetC63_2 on Top Layer "TOP_LAYER_NETC63_2_P162" (solid, remove dead copper, pour order 162): 1975,4238 2124,4238 2156,4206 2235,4206 2235,4279 1975,4279
NetC45_2 on Top Layer "TOP_LAYER_NETC45_2_P164" (solid, remove dead copper, pour order 164): 3190,3147 3274,3147 3274,3194 3227,3194 3203,3170 3190,3170
GND on Top Layer "TOP_LAYER_GND_P182" (solid, remove dead copper, pour order 182): 2035,2998 2001,3032 2001,3195 2039,3195 2126,3108 2215,3108 2232,3091 2232,3043 2187,2998
GND on Top Layer "TOP_LAYER_GND_P202" (solid, remove dead copper, pour order 202): 1558,3362.7 1476,3362.7 1476,3297 1506,3267 1506,3220 1488,3202 1267,3202 1158,3311 1158,3580 1007,3580 1007,3158 1558,3158
GND on Top Layer "TOP_LAYER_GND_P206" (solid, remove dead copper, pour order 206): 1725,3586 1675,3586 1675,3518 1750,3518 1750,3561
GND on Top Layer "TOP_LAYER_GND_P208" (solid, remove dead copper, pour order 208): 949,2693 949,2972.19 1191.15,2972.19 1191.15,3096.59 1279.97,3096.59 1301.38,3118 1301.38,3167 1782,3167 1782,2959 1496,2959 1450.2,2913.2 1423,2913.2 1375,2865.2 1375,2749 1319,2693
BAT+ on Bottom Layer "BOTTOM_LAYER_BAT+_P070" (solid, remove dead copper, pour order 70): 52,1349 52,45 634,45 634,633 cw(c734,633) 734,733 833,733 833,1349
GND on Bottom Layer "BOTTOM_LAYER_GND_P068" (solid, remove dead copper, pour order 68): 1242,2673 52,2673 52,1382 1191,1382 1242,1382
Pack+ on Bottom Layer "BOTTOM_LAYER_PACK+_P066" (solid, remove dead copper, pour order 66): 3561,1249 2359,1249 2359,106 3561,106
PDCHG_S on Bottom Layer "BOTTOM_LAYER_PDCHG_S_P000" (solid, pour order 0): 1093.26,1278 1093.26,29 2289.26,29 2289.26,1278
Pack- on Bottom Layer "BOTTOM_LAYER_PACK-_P020" (solid, remove dead copper, pour order 20): 1423,2673 3561,2673 3561,1381 1423,1381
GND on Bottom Layer "BOTTOM_LAYER_GND_P030" (solid, remove dead copper, pour order 30): 2819,2702.06 2819,3591.35 2943.84,3716.19 3035.19,3716.19 3152.84,3833.84 3152.84,4381 34,4381 34,4009 1995,3970.3 2050,2699.29
SGND on Bottom Layer "BOTTOM_LAYER_SGND_P038" (solid, remove dead copper, pour order 38): 3562,4027 3562,2694 3011,2694 3011,3571 3134,3571 3273,3710 3384,3821 3384,4027
NetQ12_3 on Bottom Layer "BOTTOM_LAYER_NETQ12_3_P126" (solid, remove dead copper, pour order 126): 343,4163 624,4163 624,4068 343,4068
NetQ11_3 on Bottom Layer "BOTTOM_LAYER_NETQ11_3_P128" (solid, remove dead copper, pour order 128): 343,4058 624,4058 624,3956.92 343,3956.92
no net on Bottom Layer "BOTTOM_LAYER_NONET_P130" (solid, remove dead copper, pour order 130): 361,4044.92 624,4044.92 624,3956.92 361,3956.92
NetQ10_3 on Bottom Layer "BOTTOM_LAYER_NETQ10_3_P132" (solid, remove dead copper, pour order 132): 343,3947 559,3947 559,3838.83 343,3838.83
NetQ9_3 on Bottom Layer "BOTTOM_LAYER_NETQ9_3_P134" (solid, remove dead copper, pour order 134): 361,3808.75 480,3808.75 480,3720.75 361,3720.75
NetQ8_3 on Bottom Layer "BOTTOM_LAYER_NETQ8_3_P136" (solid, remove dead copper, pour order 136): 345,3710 479,3710 479,3602.67 345,3602.67
NetQ7_3 on Bottom Layer "BOTTOM_LAYER_NETQ7_3_P138" (solid, remove dead copper, pour order 138): 345,3591 479,3591 479,3484.59 345,3484.59
NetQ6_3 on Bottom Layer "BOTTOM_LAYER_NETQ6_3_P140" (solid, remove dead copper, pour order 140): 345,3467.5 479,3467.5 479,3379.5 345,3379.5
NetQ5_3 on Bottom Layer "BOTTOM_LAYER_NETQ5_3_P142" (solid, remove dead copper, pour order 142): 345,3339 510,3339 510,3248.42 345,3248.42
NetQ4_3 on Bottom Layer "BOTTOM_LAYER_NETQ4_3_P144" (solid, remove dead copper, pour order 144): 345,3237 510,3237 510,3130.34 345,3130.34
NetQ3_3 on Bottom Layer "BOTTOM_LAYER_NETQ3_3_P146" (solid, remove dead copper, pour order 146): 345,3118 510,3118 510,3012.25 345,3012.25
NetQ2_3 on Bottom Layer "BOTTOM_LAYER_NETQ2_3_P148" (solid, remove dead copper, pour order 148): 345,3000 510,3000 510,2894.17 345,2894.17
NetQ1_3 on Bottom Layer "BOTTOM_LAYER_NETQ1_3_P150" (solid, remove dead copper, pour order 150): 345,2885 510,2885 510,2749 345,2749
GND on Bottom Layer "BOTTOM_LAYER_GND_P154" (solid, remove dead copper, pour order 154): 1905,3848 1905,2699 1362.14,2699 1362.14,2811.1 1234.24,2939 906,2939 891,2924 891,2902 922,2871 1234,2871 1314,2791 1314,2699 530,2699 530,3848
GND on Bottom Layer "BOTTOM_LAYER_GND_P210" (solid, remove dead copper, pour order 210): 1905,3925 1710,3925 1631,3846 1631,3818 1905,3818
GND on Bottom Layer "BOTTOM_LAYER_GND_P212" (solid, pour order 212): 1979,3278.78 1979,2699 1888,2699 1888,3278.78

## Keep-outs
Keep-Out Layer:
  text ".Layer_Name" at 577,-858.49 h60

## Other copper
Top Layer:
  rectangle net NetQ31_3: 1566,1434 1618,1526
  rectangle net C10X: 1304,3651 1419,3690
  rectangle net CHG_G: 998,1275 1116,1340
  rectangle net GND: 1433,2720 1528,2795
  text ".Layer_Name" at 577,-858.49 h60
Bottom Layer:
  rectangle net NetQ13_3: 343,4206 510,4280
  text ".Layer_Name" at 577,-858.49 h60

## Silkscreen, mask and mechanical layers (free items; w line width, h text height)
Top Overlay:
  lines w8: 2082,1942 2082,1998.05
  text "C13" at 56,4188 h50
  text "3V3" at 2124,3528 h30
  text "CLK" at 2237,3528 h30
  text "IO" at 2346,3528 h30
  text "GND" at 2419,3528 h30
  text "A" at 3553,3280.59 h50
  text "B" at 3553,3174 h50
  text "L" at 3553,3058 h50
  text "H" at 3553,2950 h50
  text "-" at 3561,2839 h72.83
  text "C0" at 57,2736 h50
  text "+" at 3553,2728 h72.83
  text "C_EN" at 3129,2715 h40
  text "CAUTION" at 2440,1854 h72.83
  text "READ USER GUIDE" at 2320,1796 h72.83
  text "BEFORE USE" at 2390,1728 h72.83
  text "BAT-" at 155,1622 h100
  text "PACK-" at 3067,1603 h100
  text "BAT+" at 152,1020 h100
  text "PACK+" at 3063,1005 h100
  text ".Layer_Name" at 577,-858.49 h60
Bottom Overlay:
  text ".Layer_Name" at 577,-858.49 h60
Top Paste:
  text ".Layer_Name" at 577,-858.49 h60
Bottom Paste:
  text ".Layer_Name" at 577,-858.49 h60
Top Solder:
  text ".Layer_Name" at 577,-858.49 h60
  text ".Layer_Name" at 577,-858.49 h60
Bottom Solder:
  text ".Layer_Name" at 577,-858.49 h60
Drill Guide:
  text ".Layer_Name" at 577,-858.49 h60
M1 Board Outline:
  the board outline again, w47.24
  text ".Layer_Name" at 577,-858.49 h60
M2 Board Dimensions:
  rectangle: 125,-400 500,-275
  rectangle: 0,-275 125,-150
  lines w7: 0,-275 1000,-275 ; 125,-400 125,-150 ; 250,-400 250,-150 ; 500,-400 500,-150 ; 750,-400 750,-150 ; 0,-400 0,-150 1000,-150 1000,-400 0,-400
  text ".Layer_Name" at 577,-858.49 h60
M3 3D STEP Top:
  text ".Layer_Name" at 577,-858.49 h60
M4 3D STEP Bottom:
  text ".Layer_Name" at 577,-858.49 h60
M5 Assembly Top:
  lines w10: -292,-930.17 6308,-930.17 ; -292,-726.83 6310,-726.83 ; -292,-523.5 -292,-1133.5 3713,-1133.5 6310,-1133.5 6310,-523.5 -291.5,-523.5 -291.5,-1133.5 1284,-1133.5 ; 2173,-1133.5 2173,-523.5 ; 3440,-726.83 3440,-523.5 ; 4280,-726.83 4280,-523.5 ; 4902,-1140 4902,-937.17
  text "COMPONENTS MARKED 'DNP' SHOULD NOT BE POPULATED." at 1153.5,-318.5 h60
  text "ASSEMBLY VARIANT:" at 1153,-434 h60
  text ".VariantName" at 2189,-434 h60
  text "PCB VIEWED FROM TOP SIDE" at -228.5,-655.67 h60
  text "BOARD #:" at 2248,-655.67 h60
  text ".PRJ_Number" at 2793.5,-655.67 h60
  text "REV:" at 3638,-655.67 h60
  text ".PCB_Rev" at 3929.5,-655.67 h60
  text "SVN REV:" at 4476,-655.67 h60
  text ".VersionControl_RevNumber" at 4982,-655.67 h60
  text "TID #:" at 2248,-859 h60
  text ".TID" at 2793.5,-859 h60
  text "PLOT NAME =" at -228.5,-1064.34 h60
  text ".plot_File_Name" at 577,-1064.34 h60
  text "GENERATED    :" at 2250,-1064.34 h60
  text ".Print_Date" at 3119.5,-1064.34 h60
  text ".Print_Time" at 3848.5,-1064.34 h60
  text "TEXAS INSTRUMENTS" at 5113,-1064.34 h60
M6 Assembly Bottom:
  lines w10: -292.5,-727.33 6309.5,-727.33 ; -290.5,-930.67 6309.5,-930.67 ; 1115.5,-1140.5 1115.5,-937.67 ; 1737.5,-727.33 1737.5,-524 ; 2577.5,-727.33 2577.5,-524 ; 3844.5,-1134 3844.5,-524 ; 4733.5,-1134 6309,-1134 6309,-524 -292.5,-524 -292.5,-1134 2304.5,-1134 6309.5,-1134 6309.5,-524
  text "COMPONENTS MARKED 'DNP' SHOULD NOT BE POPULATED." at 6102,-318 h60
  text ".VariantName" at 5058,-434 h60
  text "ASSEMBLY VARIANT:" at 6097,-434 h60
  text ".VersionControl_RevNumber" at 1035.5,-656.17 h60
  text "SVN REV:" at 1541.5,-656.17 h60
  text ".PCB_Rev" at 2088,-656.17 h60
  text "REV:" at 2379.5,-656.17 h60
  text ".PRJ_Number" at 3224,-656.17 h60
  text "BOARD #:" at 3769.5,-656.17 h60
  text "PCB VIEWED FROM BOTTOM SIDE" at 6246,-656.17 h60
  text ".TID" at 3224,-859.5 h60
  text "TID #:" at 3769.5,-859.5 h60
  text "TEXAS INSTRUMENTS" at 904.5,-1064.84 h60
  text ".Print_Time" at 2169,-1064.84 h60
  text ".Print_Date" at 2898,-1064.84 h60
  text "GENERATED    :" at 3767.5,-1064.84 h60
  text ".plot_File_Name" at 5440.5,-1064.84 h60
  text "PLOT NAME =" at 6246,-1064.84 h60
M9 Title Sheet:
  drawing of 57 lines, arcs and shapes, not listed
  text "1" at 739.84,8036.5 h70
  text "2" at 3235.5,8036.5 h70
  text "3" at 5724.84,8036.5 h70
  text "4" at 8231.51,8036.5 h70
  text "5" at 10730.5,8036.5 h70
  text "6" at 13235.5,8036.5 h70
  text "A" at -416.5,6893.5 h70
  text "A" at 14383.5,6893.5 h70
  text "B" at -416.5,4513.5 h70
  text "B" at 14383.5,4513.5 h70
  text "C" at -416.5,2138.5 h70
  text "C" at 14383.5,2138.5 h70
  text "PROJECT TITLE:" at 11343.5,277.5 h45
  text ".PRJ_Title" at 11393.5,144.17 h70
  text "DESIGNED FOR:" at 11343.5,-23.5 h45
  text ".PRJ_Customer" at 11393.5,-163.5 h70
  text "D" at -416.5,-231.5 h70
  text "D" at 14383.5,-231.5 h70
  text "FILE NAME:" at 11343.5,-323.5 h45
  text ".PCB_File_Name_No_Path" at 11393.5,-443.5 h70
  text "Texas Instruments (TI) and/or its licensors do not warrant the accuracy or completeness of this specification" at 6374,-605.34 h45
  text "ENGINEER:" at 11343.5,-613.5 h45
  text "LAYOUT BY:" at 12848.5,-613.5 h45
  text "or any information contained therein. TI and/or its licensors do not warrant that this design will meet" at 6329.01,-718 h45
  text ".PRJ_Engineer" at 11393.5,-768.49 h70
  text ".PCB_Layout" at 12899,-768.49 h70
  text "the specifications, will be suitable for your application or fit for any particular purpose, or will operate in" at 6329.01,-830.67 h45
  text ".Layer_Name" at 577,-858.49 h60
  text "ALTIUM DESIGNER VERSION:" at 12848.5,-923.5 h45
  text "an implementation. TI and/or its licensors do not warrant that the design is production worthy. You should" at 6329.01,-943.33 h45
  text "completely validate and test your design implementation to confirm the system functionality for your application." at 6374,-1056 h45
  text ".print_Scale" at 11393.5,-1056.83 h70
  text ".Application_BuildNumber" at 12899,-1056.83 h70
  text "1" at 739.84,-1263.5 h70
  text "2" at 3235.5,-1263.5 h70
  text "3" at 5724.84,-1263.5 h70
  text "4" at 8231.51,-1263.5 h70
  text "5" at 10730.5,-1263.5 h70
  text "6" at 13235.5,-1263.5 h70
M10 Fab Notes:
  drawing of 189 lines, arcs and shapes, not listed
  text "DESIGN INFORMATION" at 12382.02,6356.17 h60
  text "MIN. TRACK WIDTH:" at 11737.46,6224.05 h60
  text "8" at 12833.7,6224.05 h60
  text "MIL" at 12988.46,6224.05 h60
  text "MIN. CLEARANCE:" at 11737.46,6099.92 h60
  text "0.2" at 12773.7,6099.93 h60
  text "mm" at 12988.46,6099.92 h60
  text "MIN. VIA PAD SIZE:" at 11737.46,5975.8 h60
  text "24" at 12803.71,5975.8 h60
  text "MIL" at 12988.46,5975.8 h60
  text "0.05mm (2MIL)" at 12432.46,5845.9 h60
  text "MINIMUM ANNULAR RING" at 11408.23,5837.67 h60
  text "EXTERNAL" at 13140.46,5837.67 h60
  text "PER" at 11608.23,5727.55 h60
  text "IPC-D-275 CLASS 2 LEVEL C" at 11828.23,5727.54 h60
  text "MIL, HOLES" at 13316.46,5627.07 h60
  text "+/-" at 12924,5618.48 h60
  text "+/-" at 13778,5618.48 h60
  text "REGISTRATION TOLERANCES:" at 11408.23,5617.42 h60
  text "METAL" at 12608,5617.42 h60
  text "5" at 13184.2,5617.42 h60
  text "3" at 14017.2,5617.42 h60
  text "MIL" at 14133.46,5617.42 h60
  text "HOLE SIZE TOLERANCE (UNLESS OTHERWISE SPECIFIED):" at 11408.23,5519.1 h60
  text "+/-" at 13778,5516.23 h60
  text "3" at 14017.2,5515.17 h60
  text "MIL" at 14133.46,5515.17 h60
  text "MATERIAL:" at 11333.46,5377.52 h60
  text "FR-4 High Tg" at 12319.9,5249 h60
  text "FR-408" at 11754.46,5236.49 h60
  text "OTHER" at 13242.46,5236.49 h60
  text "62 MIL (1.6mm) +/-10%" at 12074.56,5093.46 h60
  text "THICKNESS:" at 11408.23,5085.24 h60
  text "OTHER" at 13359.46,5085.24 h60
  text "TOLERANCE:" at 11408.23,4946.92 h60
  text "ANSI IPC-6012 TYPE 3 CLASS 2" at 12434.48,4946.92 h60
  text "OTHER +/-" at 12434.46,4802.73 h60
  text "BOW & TWIST:" at 11408.23,4657.54 h60
  text "ANSI IPC-6012 TYPE 3 CLASS 2" at 12434.48,4657.54 h60
  text "OTHER +/-" at 12434.46,4510.85 h60
  text "DRILLING:" at 11333.46,4380.23 h60
  text "NC_DRILL FILES" at 13094.46,4275.04 h60
  text "REFERENCE:" at 11408.23,4271.1 h60
  text "AS SHOWN" at 12243.46,4271.1 h60
  text "OTHER" at 13392.46,4128.85 h60
  text "PTH COPPER THICKNESS:" at 11407.91,4125.32 h60
  text "20-30 um" at 12675.14,4125.32 h60
  text "BOARD FINISH:" at 11333.46,3977.73 h60
  text "SILKSCREEN:" at 11488.68,3867.6 h60
  text "TOP" at 12563.46,3867.6 h60
  text "BOTTOM" at 13074.46,3867.6 h60
  text "SILKSCREEN COLOR:" at 11488.68,3712.41 h60
  text "WHITE" at 12563.46,3712.41 h60
  text "OTHER" at 13074.46,3712.41 h60
  text "GREEN" at 12694.46,3568.96 h60
  text "OTHER" at 13312.46,3568.96 h60
  text "SOLDER RESIST COLOR:" at 11488.68,3562.1 h60
  text "MATTE" at 12694.46,3414.71 h60
  text "SEMI-GLOSS" at 13312,3414.07 h60
  text "IMMERSION GOLD (ENIG)" at 12394.46,3241.94 h60
  text "ENEPIG" at 13732,3234.72 h60
  text "SURFACE FINISH:" at 11333.46,3233.72 h60
  text "IMM. TIN/SILVER OR EQUIV" at 11663,3096.4 h60
  text "OTHER" at 13094.46,3092.47 h60
  text "ARRAY/PANEL:" at 11333.46,2937.09 h60
  text "CUT AND TRIM PER M1 BOARD OUTLINE" at 12394.46,2928.87 h60
  text "N.C. ROUTE" at 12394.46,2792.9 h60
  text "V. SCORE" at 13260.46,2792.9 h60
  text "CERTIFICATION:" at 11333.46,2663.77 h60
  text "MATERIALS AND WORKMANSHIP FOR ALL PCBS" at 12058.46,2663.77 h60
  text "TO MEET OR EXCEED THE REQUIREMENTS OF:" at 12058.46,2569.71 h60
  text "ANSI IPC-A-600F CLASS ->" at 11823.96,2441.08 h60
  text "2" at 13581.96,2441.08 h60
  text "1" at 13266.96,2439.58 h60
  text "3" at 13935.96,2439.58 h60
  text "RoHS" at 12635.96,2293.39 h60
  text "OTHER" at 13280.36,2293.39 h60
  text "PER ORDER" at 13677.42,2293.39 h60
  text "ALL BOARDS MUST MEET OR EXCEED UL94-V0 REQUIREMENTS." at 11361,2139.57 h60
  text "PCB MUST BEAR THE UL94V-0 UL REGISTERED MATERIAL ID NUMBER" at 11361,2023.5 h60
  text "ADDITIONAL REQUIREMENTS:" at 11333.46,1854.08 h60
  text "MICROSECTION:" at 11408.23,1746.95 h60
  text "YES" at 12313.96,1746.95 h60
  text "REQUIRED" at 13175.46,1602.62 h60
  text "BARE BOARD ELEC. TEST:" at 11408.23,1599.76 h60
  text "NONE" at 12713.96,1599.76 h60
  text "PER ORDER" at 13767.46,1599.76 h60
  text "XX MIL VIAS REQUIRE NON-CONDUCTIVE FILL AND PLANARIZE" at 11576.38,1394.82 h59
  text "XX MIL VIAS REQUIRE CONDUCTIVE FILL AND PLANARIZE" at 11584.38,1290.84 h60
  text "OUTER XX MIL TRACES REQUIRE 50 OHM SINGLE-ENDED IMPEDANCE" at 11583.39,1127.46 h58
  text "LAYER 2 & 3 (INNER LAYERS) XX MIL WIDE, XX MIL SPACE / TRACES REQUIRE 100 OHM DIFFERENTIAL IMPEDANCE" at 11575.39,891.74 h60
  text ".Layer_Name" at 577,-858.49 h60
M11 Gerber Information:
  lines w10: -292,-930.17 6308,-930.17 ; -292,-726.83 6310,-726.83 ; -292,-523.5 -292,-1133.5 3713,-1133.5 6310,-1133.5 6310,-523.5 -291.5,-523.5 -291.5,-1133.5 1284,-1133.5 ; 2173,-1133.5 2173,-523.5 ; 3440,-726.83 3440,-523.5 ; 4280,-726.83 4280,-523.5 ; 4902,-1140 4902,-937.17
  text "ALL ARTWORK VIEWED FROM TOP SIDE" at -228.5,-655.67 h60
  text "BOARD #:" at 2248,-655.67 h60
  text ".PRJ_Number" at 2793.5,-655.67 h60
  text "REV:" at 3638,-655.67 h60
  text ".PCB_Rev" at 3929.5,-655.67 h60
  text "SVN REV:" at 4476,-655.67 h60
  text ".VersionControl_RevNumber" at 4982,-655.67 h60
  text "LAYER NAME =" at -228.5,-858.49 h60
  text "TID #:" at 2248,-859 h60
  text ".TID" at 2793.5,-859 h60
  text "PLOT NAME =" at -228.5,-1064.34 h60
  text ".plot_File_Name" at 577,-1064.34 h60
  text "GENERATED    :" at 2250,-1064.34 h60
  text ".Print_Date" at 3119.5,-1064.34 h60
  text ".Print_Time" at 3848.5,-1064.34 h60
  text "TEXAS INSTRUMENTS" at 5113,-1064.34 h60
M12 Stackup:
  text ".Layer_Name" at 577,-858.49 h60
M13 Component Bodies Top:
  text ".Layer_Name" at 577,-858.49 h60
M14 Component Bodies Bottom:
  text ".Layer_Name" at 577,-858.49 h60
M15 Courtyards Top:
  text ".Layer_Name" at 577,-858.49 h60
M16 Courtyards Bottom:
  text ".Layer_Name" at 577,-858.49 h60
Drill Drawing:
  text ".Layer_Name" at 577,-858.49 h60
M17 Embedded Cavity:
  text ".Layer_Name" at 577,-858.49 h60
M18 Embedded Assembly:
  text ".Layer_Name" at 577,-858.49 h60
M19 Embedded Keepout:
  text ".Layer_Name" at 577,-858.49 h60

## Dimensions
0,-400 to 1000,-400 on M2 Board Dimensions
0,0 to 3613,0 on M2 Board Dimensions
0,0 to 0,4415 on M2 Board Dimensions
